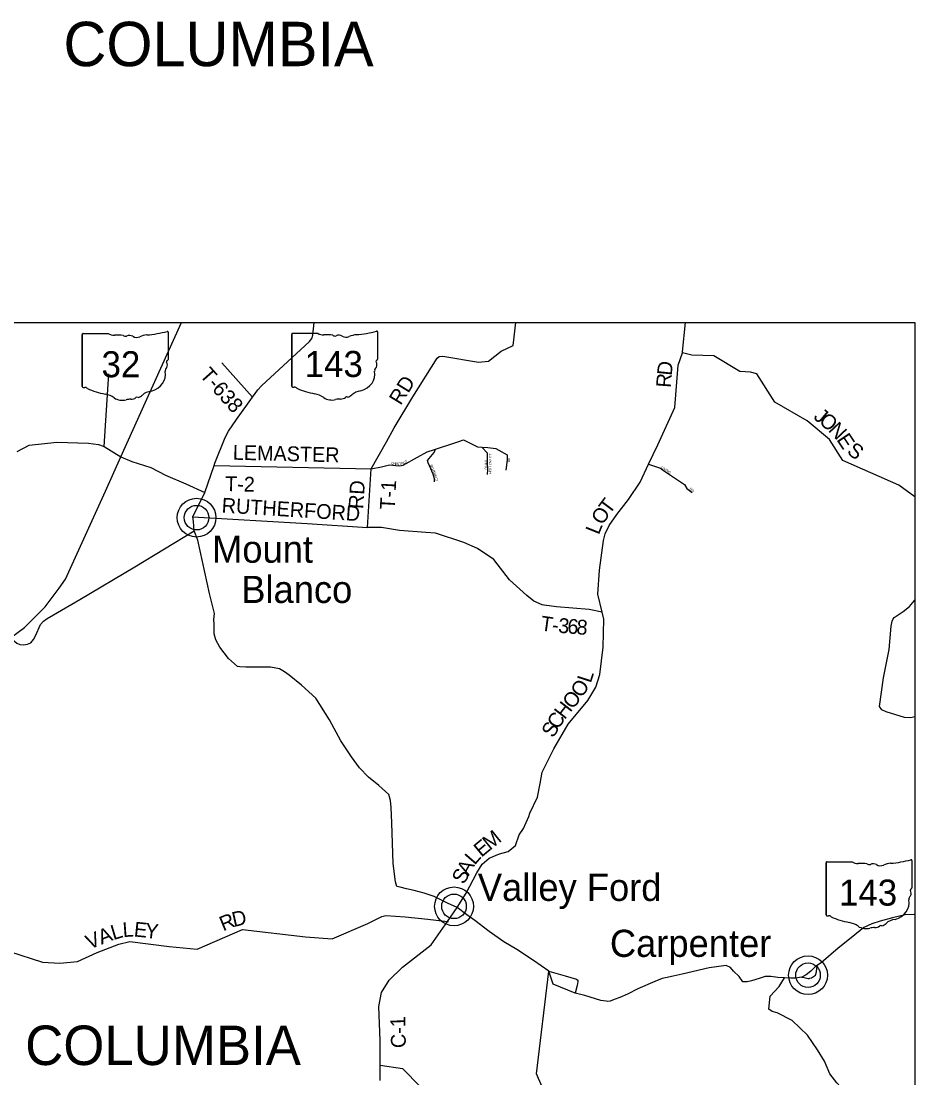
# Model space of a CAD drawing. Extents: x -15 to 405, y -40 to 87.
# Drawn here: x -11.692 to -8.262, y 18.029 to 22.085 of the extents above; entities that cross this region are included whole.
import ezdxf

# ---------------------------------------------------------------- set-up
doc = ezdxf.new("R2010")
doc.units = 0
for name, color, linetype in [('GM_P_State_Location', 7, 'Continuous'), ('GM_X_County_Road_Text', 7, 'Continuous'), ('GM_X_Major_Lake', 7, 'Continuous'), ('GM_X_Major_Lake_Text', 7, 'Continuous'), ('GM_X_Major_River', 7, 'Continuous'), ('GM_X_Minor_Lake', 7, 'Continuous'), ('GM_X_Minor_River', 7, 'Continuous'), ('GM_X_State_Location', 7, 'Continuous'), ('GM_X_Township', 7, 'Continuous'), ('GM_X_Township_ROW', 7, 'Continuous'), ('GM_X_Township_Subdivision', 7, 'Continuous'), ('GM_X_Township_Subdivision_Text', 7, 'Continuous'), ('GM_X_Township_Text', 7, 'Continuous'), ('GM_X_Unincorporated_Location', 7, 'Continuous')]:
    doc.layers.add(name, color=color, linetype=linetype)

msp = doc.modelspace()

# ---------------------------------------------------------------- linework, layer by layer
at = {"layer": 'GM_P_State_Location'}
for points in [[(-10.3486, 20.367), (-10.2897, 20.4708), (-10.2607, 20.5245), (-10.189, 20.6427), (-10.0958, 20.7919), (-10.0876, 20.7982), (-10.0738, 20.7992), (-9.9363, 20.7767), (-9.8983, 20.7807), (-9.8497, 20.8189), (-9.804, 20.84), (-9.7938, 20.9289)], [(-8.2623, 20.2592), (-8.3233, 20.3041), (-8.5383, 20.3988), (-8.5902, 20.4795), (-8.6757, 20.551), (-8.7992, 20.6225), (-8.8689, 20.7317), (-8.8925, 20.7379), (-8.9339, 20.7409), (-9.0338, 20.8012), (-9.1182, 20.8033), (-9.1543, 20.8125)], [(-10.804, 20.6413), (-10.9223, 20.7741)], [(-11.3729, 20.4523), (-11.3551, 20.7315)], [(-11.7067, 20.4335), (-11.6607, 20.4578), (-11.5544, 20.4696), (-11.4333, 20.4651), (-11.3946, 20.4603), (-11.3729, 20.4523)], [(-11.3729, 20.4523), (-11.3092, 20.4127)], [(-11.3092, 20.4127), (-11.2669, 20.3947), (-11.1944, 20.3721), (-11.1374, 20.3424), (-11.0602, 20.3092), (-10.9875, 20.2761)], [(-11.0326, 20.1825), (-10.5938, 20.1565), (-10.3621, 20.1415), (-10.3486, 20.367)], [(-10.9514, 20.3802), (-10.3486, 20.367)], [(-10.1388, 20.1222), (-10.2393, 20.1299), (-10.3086, 20.1417), (-10.3621, 20.1415)], [(-9.4625, 19.817), (-9.5123, 19.8273), (-9.6371, 19.8369), (-9.6853, 19.8438)], [(-8.2623, 19.4144), (-8.2778, 19.4111), (-8.3014, 19.412), (-8.3727, 19.434), (-8.389, 19.4421), (-8.398, 19.4542), (-8.3825, 19.5641), (-8.3613, 19.6733), (-8.3527, 19.7629), (-8.3489, 19.7822), (-8.346, 19.7905), (-8.3417, 19.7961), (-8.3066, 19.8192), (-8.2831, 19.8388), (-8.2694, 19.8538), (-8.2623, 19.8628)], [(-11.7363, 18.5142), (-11.6098, 18.4729), (-11.5433, 18.4691), (-11.4753, 18.476), (-11.3998, 18.5099), (-11.3174, 18.5426), (-11.2753, 18.5529), (-11.1233, 18.5332), (-11.017, 18.5234), (-10.8427, 18.5983), (-10.6008, 18.5707), (-10.4987, 18.5632), (-10.362, 18.6218), (-10.3074, 18.6486), (-10.2919, 18.6521), (-10.2181, 18.647), (-10.1316, 18.6386), (-10.056, 18.6287), (-10.0537, 18.6284)], [(-9.1653, 16.608), (-9.1986, 16.6073), (-9.2895, 16.6146), (-9.338, 16.6373), (-9.4395, 16.7094), (-9.4747, 16.8339), (-9.4804, 16.9288), (-9.4733, 16.982), (-9.4872, 17.0673), (-9.5096, 17.0974), (-9.5307, 17.1173), (-9.5328, 17.1252), (-9.5398, 17.1513), (-9.5154, 17.2124), (-9.4962, 17.3291), (-9.4833, 17.4044), (-9.4997, 17.5413), (-9.5484, 17.5844), (-9.6358, 17.648), (-9.6476, 17.6847), (-9.6484, 17.8939), (-9.7143, 18.045), (-9.6672, 18.4388)], [(-9.6672, 18.4388), (-9.604, 18.4206), (-9.5605, 18.4078), (-9.5555, 18.4042), (-9.5555, 18.3991), (-9.5587, 18.3831), (-9.566, 18.3542)], [(-10.3137, 18.0778), (-10.228, 18.0646), (-10.1595, 17.9948)]]:
    msp.add_lwpolyline(points, dxfattribs=at)
at = {"layer": 'GM_X_Major_Lake_Text'}
for points in [[(-9.6853, 19.8438), (-9.6856, 19.8439), (-9.693, 19.845), (-9.7242, 19.8587), (-9.7508, 19.8811), (-9.8172, 19.9411), (-9.8774, 20.019), (-9.9409, 20.0616), (-9.9936, 20.0841), (-10.1012, 20.1193), (-10.1385, 20.1222), (-10.1388, 20.1222)], [(-8.6509, 18.4185), (-8.6507, 18.4186), (-8.6435, 18.4233), (-8.6401, 18.4365), (-8.6378, 18.4502), (-8.6353, 18.4614)]]:
    msp.add_lwpolyline(points, dxfattribs=at)
at = {"layer": 'GM_X_Major_River'}
for points in [[(-10.1062, 20.4413), (-10.1012, 20.4429), (-10.0275, 20.4668), (-10.012, 20.4719), (-9.994, 20.4777), (-9.9402, 20.4515), (-9.9387, 20.4514)], [(-9.9387, 20.4514), (-9.9235, 20.45), (-9.9009, 20.4481), (-9.87, 20.4453), (-9.8263, 20.4211), (-9.8266, 20.402), (-9.8323, 20.3613)], [(-9.9027, 20.3456), (-9.9024, 20.3493), (-9.9015, 20.3592), (-9.9022, 20.3963), (-9.9022, 20.4126), (-9.9022, 20.4271), (-9.9235, 20.45)], [(-10.3486, 20.367), (-10.3089, 20.374), (-10.2782, 20.3817), (-10.2414, 20.3785), (-10.2325, 20.3802), (-10.226, 20.3815), (-10.1704, 20.411), (-10.1332, 20.4325), (-10.1062, 20.4413)], [(-10.1053, 20.3169), (-10.1057, 20.3287), (-10.1107, 20.3463), (-10.1293, 20.3899), (-10.1329, 20.3986), (-10.1067, 20.43), (-10.1012, 20.4429)], [(-9.2838, 20.3844), (-9.2382, 20.3697), (-9.2227, 20.3584), (-9.1468, 20.3068), (-9.1377, 20.2916), (-9.1165, 20.2765)], [(-8.6681, 18.411), (-8.668, 18.411), (-8.6648, 18.4111), (-8.6587, 18.4134), (-8.6509, 18.4185)], [(-8.6963, 18.4155), (-8.6864, 18.4142), (-8.6723, 18.4108), (-8.6681, 18.411)]]:
    msp.add_lwpolyline(points, dxfattribs=at)
at = {"layer": 'GM_X_State_Location'}
for points in [[(-11.5463, 19.9093), (-11.5215, 19.9428), (-11.3683, 20.2808), (-11.3092, 20.4127), (-11.1562, 20.7537), (-11.0771, 20.9289)], [(-12.2933, 19.3861), (-12.2336, 19.4156), (-11.9565, 19.5816), (-11.7662, 19.6938), (-11.7328, 19.7183), (-11.6795, 19.7573), (-11.5995, 19.8376), (-11.5463, 19.9093)], [(-8.2623, 18.6562), (-8.2653, 18.6562), (-8.2995, 18.6552), (-8.3477, 18.6427), (-8.396, 18.631), (-8.4268, 18.62), (-8.4579, 18.6056), (-8.5073, 18.5662), (-8.5571, 18.5272), (-8.6214, 18.4711), (-8.6353, 18.4614), (-8.6449, 18.4548), (-8.6613, 18.4389), (-8.6792, 18.4245), (-8.6963, 18.4155), (-8.7221, 18.412), (-8.738, 18.412), (-8.7622, 18.4128), (-8.7885, 18.4137), (-8.8155, 18.4182), (-8.8364, 18.4178), (-8.86, 18.4099), (-8.8896, 18.402), (-8.9063, 18.3978), (-8.923, 18.3975), (-8.9367, 18.4176), (-8.9579, 18.4389), (-8.9693, 18.4526), (-8.986, 18.4602), (-9.0513, 18.4519), (-9.1554, 18.4274), (-9.1903, 18.4195), (-9.2193, 18.4134)], [(-9.2193, 18.4134), (-9.2194, 18.4133), (-9.2314, 18.4108), (-9.2603, 18.3991), (-9.3256, 18.3711), (-9.3655, 18.3506), (-9.394, 18.3377), (-9.4164, 18.3294), (-9.4316, 18.3234), (-9.4411, 18.3226), (-9.4469, 18.3234)]]:
    msp.add_lwpolyline(points, dxfattribs=at)
at = {"layer": 'GM_X_Township'}
for p, q in [((-15.0623, 20.9289), (-8.2623, 20.9289)), ((-8.2623, 20.9289), (-8.2623, 14.1289))]:
    msp.add_line(p, q, dxfattribs=at)
at = {"layer": 'GM_X_Township_Subdivision'}
for p, q in [((-11.1277, 20.8911), (-11.1277, 20.7864)), ((-10.3238, 20.8921), (-10.3238, 20.7874)), ((-11.4573, 20.8827), (-11.4573, 20.6825)), ((-11.4573, 20.6825), (-11.4573, 20.8827)), ((-11.4573, 20.6825), (-11.4573, 20.8827)), ((-11.4541, 20.8861), (-11.3576, 20.8861)), ((-10.6534, 20.8837), (-10.6534, 20.6836)), ((-10.6534, 20.6836), (-10.6534, 20.8837)), ((-10.6534, 20.6836), (-10.6534, 20.8837)), ((-10.6501, 20.8872), (-10.5536, 20.8872)), ((-11.1278, 20.7864), (-11.1277, 20.7864)), ((-10.3238, 20.7875), (-10.3238, 20.7874)), ((-8.2734, 18.863), (-8.2734, 18.7583)), ((-8.603, 18.8546), (-8.603, 18.6545)), ((-8.603, 18.6545), (-8.603, 18.8546)), ((-8.603, 18.6545), (-8.603, 18.8546)), ((-8.5998, 18.8581), (-8.5032, 18.8581)), ((-8.2734, 18.7584), (-8.2734, 18.7583))]:
    msp.add_line(p, q, dxfattribs=at)
for centre, major_axis, start_param, end_param in [((-11.2451, 21.1589), (0.3495, 0), 4.814394, 5.042369), ((-11.1314, 20.8915), (0.00367, 0), 6.141152, 7.989035), ((-10.4412, 21.16), (0.3495, 0), 4.814394, 5.042369), ((-10.3274, 20.8925), (0.00367, 0), 6.141152, 7.989035), ((-11.4535, 20.8831), (0.00382, 0), 1.712693, 3.28349), ((-11.3346, 20.9093), (0.037, 0), 4.042523, 4.731795), ((-11.3223, 20.7737), (0.133, 0), 1.404758, 1.657858), ((-11.2921, 20.8841), (0.0107, 0), 3.836095, 5.185415), ((-11.2764, 20.861), (0.0222, 0), 0.950623, 2.079405), ((-11.2478, 20.8927), (0.0267, 0), 4.081561, 5.145723), ((-11.2006, 20.825), (0.0703, 0), 1.699011, 2.107814), ((-10.6496, 20.8841), (0.00382, 0), 1.712693, 3.28349), ((-10.5306, 20.9104), (0.037, 0), 4.042523, 4.731795), ((-10.5183, 20.7748), (0.133, 0), 1.404758, 1.657858), ((-10.4881, 20.8852), (0.0107, 0), 3.836095, 5.185415), ((-10.4725, 20.862), (0.0222, 0), 0.950623, 2.079405), ((-10.4438, 20.8938), (0.0267, 0), 4.081561, 5.145723), ((-10.3966, 20.826), (0.0703, 0), 1.699011, 2.107814), ((-11.1286, 20.7787), (0.00568, 0), 1.883978, 3.671073), ((-11.1647, 20.7655), (0.0341, 0), 5.934695, 6.695948), ((-11.1317, 20.786), (0.00393, 0), 5.05454, 6.418171), ((-10.3246, 20.7797), (0.00568, 0), 1.883978, 3.671073), ((-10.3607, 20.7665), (0.0341, 0), 5.934695, 6.695948), ((-10.3277, 20.787), (0.00393, 0), 5.05454, 6.418171), ((-11.2256, 20.7292), (0.0874, 0), 5.101752, 6.440018), ((-11.1146, 20.7426), (0.0248, 0), 2.387724, 3.262537), ((-10.4216, 20.7303), (0.0874, 0), 5.101752, 6.440018), ((-10.3106, 20.7436), (0.0248, 0), 2.387724, 3.262537), ((-11.4535, 20.6821), (0.00385, 0), 3.00124, 4.508301), ((-11.4529, 20.7026), (0.0294, 0), 4.665946, 4.897461), ((-11.4469, 20.671), (0.0106, 0), 0.519207, 1.627899), ((-11.3131, 20.8508), (0.2524, 0), 4.195997, 4.488961), ((-11.3883, 20.5926), (0.079, 0), 0.823519, 1.323587), ((-11.2494, 20.6631), (0.0282, 0), 4.937069, 5.64225), ((-11.1887, 20.6263), (0.0479, 0), 1.647645, 2.488434), ((-10.6495, 20.6832), (0.00385, 0), 3.00124, 4.508301), ((-10.649, 20.7036), (0.0294, 0), 4.665946, 4.897461), ((-10.6429, 20.672), (0.0106, 0), 0.519207, 1.627899), ((-10.5091, 20.8518), (0.2524, 0), 4.195997, 4.488961), ((-10.5844, 20.5937), (0.079, 0), 0.823519, 1.323587), ((-10.4454, 20.6642), (0.0282, 0), 4.937069, 5.64225), ((-10.3847, 20.6274), (0.0479, 0), 1.647645, 2.488434), ((-11.3029, 20.67), (0.0501, 0), 4.026481, 4.996735), ((-11.274, 20.6008), (0.0412, 0), 1.495662, 1.94098), ((-11.2703, 20.655), (0.0267, 0), 4.691044, 5.507374), ((-11.2462, 20.6356), (0.00752, 0), 1.147584, 2.315152), ((-10.499, 20.6711), (0.0501, 0), 4.026481, 4.996735), ((-10.47, 20.6019), (0.0412, 0), 1.495662, 1.94098), ((-10.4663, 20.6561), (0.0267, 0), 4.691044, 5.507374), ((-10.4422, 20.6367), (0.00752, 0), 1.147584, 2.315152), ((-8.3908, 19.1309), (0.3495, 0), 4.814394, 5.042369), ((-8.2771, 18.8635), (0.00367, 0), 6.141152, 7.989035), ((-8.5992, 18.8551), (0.00382, 0), 1.712693, 3.28349), ((-8.4802, 18.8813), (0.037, 0), 4.042523, 4.731795), ((-8.468, 18.7457), (0.133, 0), 1.404758, 1.657858), ((-8.4378, 18.8561), (0.0107, 0), 3.836095, 5.185415), ((-8.4221, 18.833), (0.0222, 0), 0.950623, 2.079405), ((-8.3934, 18.8647), (0.0267, 0), 4.081561, 5.145723), ((-8.3462, 18.797), (0.0703, 0), 1.699011, 2.107814), ((-8.2743, 18.7507), (0.00568, 0), 1.883978, 3.671073), ((-8.3104, 18.7374), (0.0341, 0), 5.934695, 6.695948), ((-8.2773, 18.7579), (0.00393, 0), 5.05454, 6.418171), ((-8.3712, 18.7012), (0.0874, 0), 5.101752, 6.440018), ((-8.2603, 18.7145), (0.0248, 0), 2.387724, 3.262537), ((-8.5992, 18.6541), (0.00385, 0), 3.00124, 4.508301), ((-8.5986, 18.6745), (0.0294, 0), 4.665946, 4.897461), ((-8.5926, 18.643), (0.0106, 0), 0.519207, 1.627899), ((-8.4588, 18.8228), (0.2524, 0), 4.195997, 4.488961), ((-8.534, 18.5646), (0.079, 0), 0.823519, 1.323587), ((-8.395, 18.6351), (0.0282, 0), 4.937069, 5.64225), ((-8.3344, 18.5983), (0.0479, 0), 1.647645, 2.488434), ((-8.4486, 18.642), (0.0501, 0), 4.026481, 4.996735), ((-8.4196, 18.5728), (0.0412, 0), 1.495662, 1.94098), ((-8.416, 18.627), (0.0267, 0), 4.691044, 5.507374), ((-8.3918, 18.6076), (0.00752, 0), 1.147584, 2.315152)]:
    msp.add_ellipse(centre, major_axis=major_axis, ratio=0.8, start_param=start_param, end_param=end_param, dxfattribs=at)
at = {"layer": 'GM_X_Township_Subdivision_Text'}
for centre, radius in [((-11.0187, 20.1794), 0.0744), ((-11.0187, 20.1794), 0.0472), ((-10.0307, 18.6874), 0.0744), ((-10.0307, 18.6874), 0.0472), ((-8.6722, 18.4231), 0.0744), ((-8.6722, 18.4231), 0.0472)]:
    msp.add_circle(centre, radius, dxfattribs=at)
at = {"layer": 'GM_X_Township_Text'}
for points in [[(-10.018, 18.6824), (-9.9839, 18.7382), (-9.9432, 18.8155), (-9.9224, 18.8497), (-9.8959, 18.8722), (-9.8558, 18.8891), (-9.8235, 18.898), (-9.7951, 18.9213), (-9.7812, 18.9616), (-9.7635, 18.9867), (-9.7438, 19.0327), (-9.7398, 19.0457), (-9.7105, 19.1069), (-9.7, 19.1593), (-9.693, 19.2022), (-9.6474, 19.2916), (-9.5928, 19.3871), (-9.5172, 19.4778), (-9.4866, 19.5288), (-9.4707, 19.578), (-9.4584, 19.6818), (-9.4562, 19.7903), (-9.4625, 19.817), (-9.4786, 19.8851), (-9.4726, 19.9784), (-9.4567, 20.0912), (-9.4512, 20.1174), (-9.4357, 20.1493), (-9.4055, 20.1916), (-9.3606, 20.2494), (-9.316, 20.3161), (-9.2838, 20.3844), (-9.2486, 20.4591), (-9.1831, 20.6028), (-9.1709, 20.7652), (-9.1543, 20.8125), (-9.1533, 20.8154), (-9.1424, 20.9289)], [(-11.568, 19.8058), (-11.5676, 19.8061), (-11.4671, 19.8656), (-11.2553, 19.991), (-11.0285, 20.1291)], [(-11.8944, 19.656), (-11.8445, 19.6782), (-11.8209, 19.7006), (-11.8046, 19.7169), (-11.7922, 19.7281), (-11.7796, 19.734), (-11.7687, 19.7338), (-11.7575, 19.731), (-11.7328, 19.7183), (-11.7078, 19.6972), (-11.6963, 19.6926), (-11.6831, 19.6916), (-11.6675, 19.6937), (-11.6542, 19.6995), (-11.644, 19.7115), (-11.6364, 19.7254), (-11.617, 19.7687), (-11.6057, 19.7819), (-11.5916, 19.7919), (-11.568, 19.8058)], [(-10.3137, 18.0186), (-10.3137, 18.0778), (-10.3138, 18.1719), (-10.3193, 18.3028), (-10.3085, 18.3571), (-10.2802, 18.4043), (-10.228, 18.4539), (-10.119, 18.5399), (-10.056, 18.6287), (-10.018, 18.6824)], [(-8.4252, 17.7077), (-8.4311, 17.7384), (-8.4392, 17.7805), (-8.4527, 17.8206), (-8.4846, 17.8979), (-8.4965, 17.9278), (-8.5137, 17.9558), (-8.5614, 18.0103), (-8.5889, 18.0451), (-8.6085, 18.0932), (-8.636, 18.1371), (-8.6738, 18.193), (-8.7329, 18.2489), (-8.7912, 18.2783), (-8.8098, 18.2839), (-8.8228, 18.2922), (-8.8169, 18.343), (-8.7836, 18.3792), (-8.7622, 18.4128)]]:
    msp.add_lwpolyline(points, dxfattribs=at)
at = {"layer": 'GM_X_Unincorporated_Location'}
msp.add_lwpolyline([(-9.4469, 18.3234), (-9.4471, 18.3234), (-9.4669, 18.3261), (-9.5284, 18.3448), (-9.566, 18.3542), (-9.6506, 18.3884), (-9.6672, 18.4388), (-9.7255, 18.4795), (-9.7902, 18.5213), (-9.8399, 18.5507), (-9.8958, 18.5915), (-9.9514, 18.633), (-9.982, 18.6542), (-10.018, 18.6824), (-10.0554, 18.699), (-10.1074, 18.7246), (-10.1447, 18.7374), (-10.1836, 18.748), (-10.2125, 18.7549), (-10.2373, 18.7606), (-10.2502, 18.7639), (-10.2554, 18.7813), (-10.2645, 18.8515), (-10.2698, 19.0078), (-10.2724, 19.067), (-10.2746, 19.0939), (-10.2813, 19.1162), (-10.3197, 19.1511), (-10.3592, 19.1833), (-10.3934, 19.219), (-10.4243, 19.2608), (-10.4645, 19.3233), (-10.508, 19.4033), (-10.5606, 19.4869), (-10.6162, 19.5368), (-10.6634, 19.5753), (-10.6814, 19.5877), (-10.7, 19.5992), (-10.7347, 19.6053), (-10.7894, 19.6054), (-10.8297, 19.6053), (-10.8532, 19.6069), (-10.862, 19.6087), (-10.8958, 19.6387), (-10.9293, 19.6823), (-10.9448, 19.7103), (-10.9512, 19.7333), (-10.9516, 19.772), (-10.9518, 19.7884), (-10.9496, 19.8121), (-10.9693, 19.8887), (-11.0142, 20.0935), (-11.0285, 20.1291), (-11.0302, 20.1647), (-11.0326, 20.1825), (-10.9875, 20.2761), (-10.9514, 20.3802), (-10.9486, 20.3885), (-10.9085, 20.4876), (-10.896, 20.5119), (-10.865, 20.5564), (-10.804, 20.6413), (-10.7832, 20.6704), (-10.7699, 20.6852), (-10.5858, 20.8552), (-10.5767, 20.8677), (-10.5729, 20.8795), (-10.5669, 20.9289)], dxfattribs=at)

# ---------------------------------------------------------------- texts
at = {"layer": 'GM_X_County_Road_Text'}
for height, p in [(0.17045, (-11.5297, 21.9124)), (0.15152, (-11.6764, 18.0783))]:
    msp.add_text('COLUMBIA', height=height, rotation=0, dxfattribs=at).set_placement(p)
at = {"layer": 'GM_X_Major_Lake'}
for s, rotation, p in [('HOLLOW CT', 90, (-9.887, 20.347)), ('D', 269.0164, (-9.8248, 20.4095)), ('C', 354.2097, (-10.2721, 20.3836)), ('H', 354.2253, (-10.2647, 20.3829)), ('E', 354.2369, (-10.2564, 20.382)), ('S', 354.2241, (-10.2498, 20.3813)), ('T', 9.0541, (-10.2405, 20.3807)), ('N', 17.2805, (-10.2324, 20.3821)), ('U', 27.6127, (-10.2227, 20.3853)), ('T', 27.3959, (-10.2154, 20.3892)), ('B', 292.2705, (-10.1233, 20.3809)), ('I', 292.2957, (-10.1205, 20.374)), ('G', 292.2803, (-10.1189, 20.3701)), ('P', 292.2702, (-10.1148, 20.3601)), ('QUAIL', 90, (-9.9032, 20.3636)), ('R', 266.2812, (-9.825, 20.4013)), ('LIVING', 325.9783, (-9.2372, 20.3708)), ('I', 292.2799, (-10.1123, 20.3539)), ('N', 289.4788, (-10.1107, 20.3502)), ('E', 286.1706, (-10.108, 20.3425)), ('C', 283.3295, (-10.1055, 20.3338)), ('T', 279.8038, (-10.1038, 20.3266)), ('RD', 321.3438, (-9.128, 20.2883))]:
    msp.add_text(s, height=0.00947, rotation=rotation, dxfattribs=at).set_placement(p)
at = {"layer": 'GM_X_Minor_Lake'}
for s, height, rotation, p in [('D', 0.0568, 84.1836, (-9.1955, 20.723)), ('R', 0.0568, 85.7575, (-9.1989, 20.6769)), ('T', 0.0568, 53.0967, (-9.4342, 20.1891)), ('O', 0.0568, 57.1505, (-9.4607, 20.148)), ('L', 0.0568, 68.1683, (-9.4752, 20.1111)), ('O', 0.0568, 56.8922, (-9.5403, 19.4851)), ('L', 0.0568, 72.2732, (-9.5059, 19.542)), ('O', 0.0568, 50.8264, (-9.5758, 19.441)), ('H', 0.0568, 52.0212, (-9.6063, 19.4019)), ('C', 0.0568, 57.451, (-9.6306, 19.3637)), ('S', 0.0568, 59.997, (-9.6495, 19.3311)), ('E', 0.0568, 39.6316, (-9.9256, 18.8737)), ('M', 0.0568, 38.89, (-9.893, 18.9007)), ('L', 0.0568, 49.1156, (-9.9517, 18.8433)), ('S', 0.0568, 62.0452, (-9.9923, 18.7687)), ('A', 0.0568, 60.5389, (-9.9745, 18.8023)), ('C-1', 0.05682, 91.354, (-10.2153, 18.144))]:
    msp.add_text(s, height=height, rotation=rotation, dxfattribs=at).set_placement(p)
at = {"layer": 'GM_X_Minor_River'}
for s, height, rotation, p in [('T-638', 0.05682, 311.6339, (-11.0094, 20.7248)), ('RD', 0.05682, 58.359, (-10.2352, 20.6079)), ('J', 0.0568, 319.9566, (-8.6543, 20.5619)), ('O', 0.0568, 319.5872, (-8.6339, 20.5448)), ('N', 0.0568, 313.1889, (-8.5971, 20.5135)), ('E', 0.0568, 303.3656, (-8.5644, 20.4791)), ('LEMASTER', 0.05682, 358.5677, (-10.8801, 20.4019)), ('S', 0.0568, 323.1327, (-8.5265, 20.4281)), ('T-2', 0.05682, 358.5669, (-10.9098, 20.2817)), ('RD', 0.05682, 86.5467, (-10.3789, 20.2116)), ('T-1', 0.05682, 86.6615, (-10.2589, 20.2087)), ('RUTHERFORD', 0.05682, 356.3915, (-10.9235, 20.1994)), ('T', 0.0568, 351.9899, (-9.7012, 19.7469)), ('-', 0.0568, 354.1681, (-9.6568, 19.7407)), ('3', 0.0568, 354.8519, (-9.6328, 19.7383)), ('6', 0.0568, 355.471, (-9.5973, 19.7351)), ('8', 0.0568, 355.6151, (-9.5623, 19.7323)), ('D', 0.0568, 12.8947, (-10.8758, 18.608)), ('L', 0.0568, 4.0618, (-11.3007, 18.5691)), ('E', 0.0568, 354.1014, (-11.2609, 18.5722)), ('Y', 0.0568, 353.1425, (-11.2189, 18.5679)), ('R', 0.0568, 22.2935, (-10.9166, 18.5911)), ('V', 0.0568, 22.9345, (-11.4293, 18.5206)), ('A', 0.0568, 21.3056, (-11.3836, 18.5399)), ('L', 0.0568, 16.4369, (-11.3382, 18.5577))]:
    msp.add_text(s, height=height, rotation=rotation, dxfattribs=at).set_placement(p)
at = {"layer": 'GM_X_Township_ROW'}
for s, height, p in [('Mount', 0.10417, (-10.9591, 20.0064)), ('Blanco', 0.10417, (-10.8471, 19.8519)), ('Valley Ford', 0.104167, (-9.9392, 18.7082)), ('Carpenter', 0.10417, (-9.4325, 18.4934))]:
    msp.add_text(s, height=height, rotation=0, dxfattribs=at).set_placement(p)
at = {"layer": 'GM_X_Township_Subdivision'}
for s, p in [('32', (-11.3834, 20.7183)), ('143', (-10.6038, 20.7193)), ('143', (-8.5534, 18.6902))]:
    msp.add_text(s, height=0.1, dxfattribs=at).set_placement(p)

doc.saveas('drawing.dxf')
